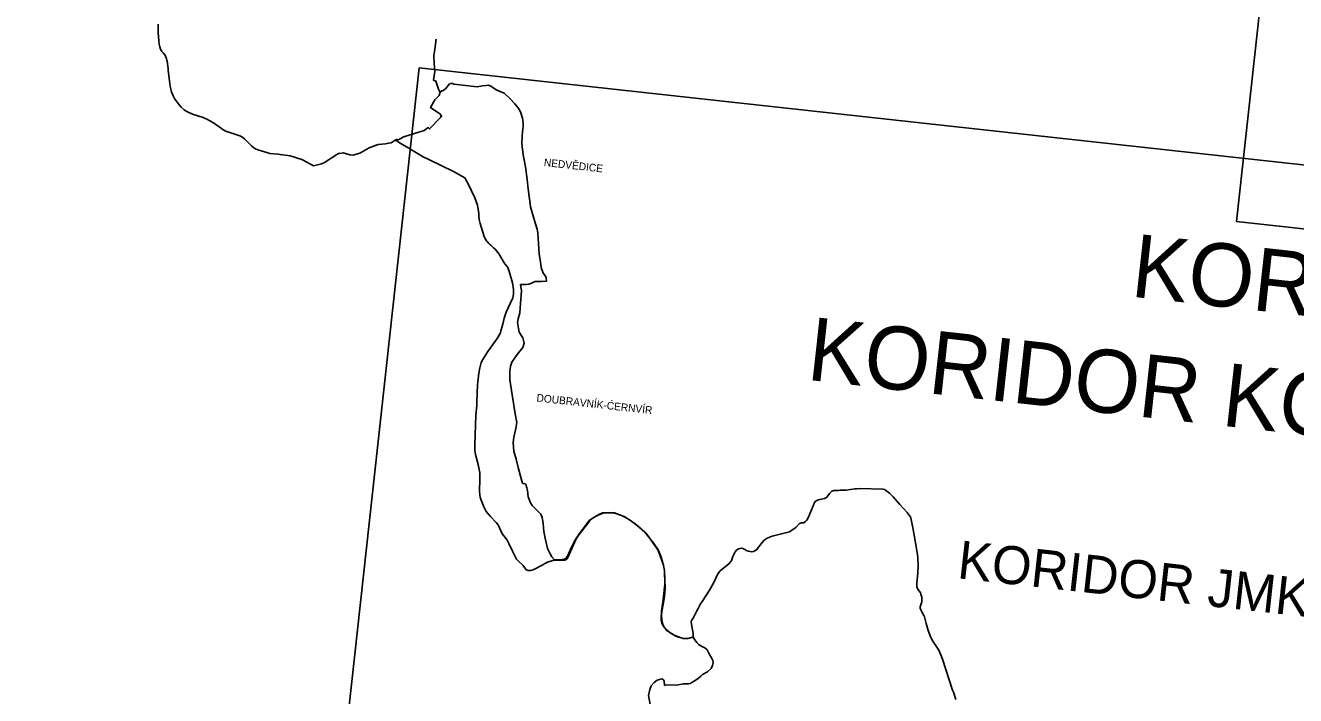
# Model space of a CAD drawing. Extents: x -678204 to -526855, y -1228851 to -1110393.
# Drawn here: x -617877 to -607858, y -1134277 to -1128993 of the extents above; entities that cross this region are included whole.
import ezdxf

# ---------------------------------------------------------------- set-up
doc = ezdxf.new("R2010")
doc.units = 0
for name, color, linetype in [('00_n_cyklo popisy', 7, 'Continuous'), ('00_n_cyklo popisy detaily', 7, 'Continuous'), ('00_n_cyklo prujezdne podminecne rekreacni hlavni', 7, 'Continuous'), ('00_n_cyklo prujezdne rekreacni hlavni', 7, 'Continuous'), ('00_n_cyklo realizace rekreacni hlavni', 7, 'Continuous'), ('00_n_cyklo studie rekreacni hlavni', 7, 'Continuous'), ('00_n_cyklo trasovani rekreacni hlavni', 7, 'Continuous'), ('00_n_legenda popisy_hlavni', 7, 'Continuous'), ('_HELP BIG', 7, 'Continuous'), ('trasy_0001', 7, 'Continuous')]:
    doc.layers.add(name, color=color, linetype=linetype)

msp = doc.modelspace()

# ---------------------------------------------------------------- linework, layer by layer
at = {"layer": '00_n_cyklo prujezdne podminecne rekreacni hlavni'}
for points in [[(-613956, -1129833), (-613951, -1129791), (-613952, -1129763), (-613955, -1129724), (-613973, -1129675), (-613990, -1129643), (-614017, -1129612), (-614054, -1129572), (-614102, -1129526), (-614163, -1129500), (-614183, -1129488), (-614205, -1129472), (-614224, -1129465), (-614242, -1129466), (-614273, -1129470), (-614314, -1129477), (-614498, -1129456), (-614507, -1129452), (-614522, -1129450), (-614532, -1129453), (-614562, -1129491), (-614582, -1129505), (-614603, -1129513)], [(-613905, -1130329), (-613906, -1130320), (-613915, -1130260), (-613920, -1130209), (-613933, -1130109), (-613940, -1130067), (-613950, -1130013), (-613960, -1129947), (-613962, -1129919), (-613959, -1129868), (-613956, -1129833)], [(-613768, -1131009), (-613770, -1130982), (-613778, -1130964), (-613794, -1130946), (-613808, -1130902), (-613815, -1130856), (-613824, -1130796), (-613834, -1130628), (-613841, -1130600), (-613857, -1130549), (-613874, -1130487), (-613892, -1130423), (-613901, -1130358), (-613905, -1130329)]]:
    msp.add_lwpolyline(points, dxfattribs=at)
at = {"layer": '00_n_cyklo prujezdne rekreacni hlavni'}
for points in [[(-614603, -1129513), (-614611, -1129511), (-614618, -1129496), (-614639, -1129432), (-614645, -1129429), (-614658, -1129425), (-614649, -1129356), (-614652, -1129291), (-614655, -1129233), (-614647, -1129181), (-614637, -1129101)], [(-614603, -1129513), (-614607, -1129527), (-614613, -1129546), (-614649, -1129580), (-614682, -1129640), (-614607, -1129690), (-614595, -1129706), (-614604, -1129720), (-614689, -1129809), (-614701, -1129799), (-614733, -1129822), (-614884, -1129868), (-614899, -1129873), (-614911, -1129881), (-614927, -1129891), (-614932, -1129893), (-614939, -1129894), (-614948, -1129892), (-614954, -1129893), (-614958, -1129897), (-614959, -1129906)], [(-613972, -1131035), (-613928, -1131036), (-613906, -1131033), (-613890, -1131029), (-613874, -1131019), (-613857, -1131012), (-613835, -1131011), (-613807, -1131012), (-613768, -1131009)], [(-610539, -1134307), (-610557, -1134251), (-610563, -1134234), (-610644, -1133990), (-610656, -1133955), (-610672, -1133919), (-610719, -1133848), (-610736, -1133820), (-610756, -1133764), (-610771, -1133709), (-610785, -1133657), (-610790, -1133645), (-610807, -1133617), (-610813, -1133601), (-610818, -1133588), (-610818, -1133577), (-610805, -1133538), (-610807, -1133502), (-610813, -1133477), (-610816, -1133467), (-610836, -1133440), (-610845, -1133422), (-610846, -1133390), (-610838, -1133308), (-610836, -1133255), (-610837, -1133191), (-610839, -1133168), (-610847, -1133117), (-610875, -1132968), (-610893, -1132876), (-610899, -1132866), (-610923, -1132834), (-610980, -1132771), (-611033, -1132711), (-611062, -1132680), (-611092, -1132656), (-611100, -1132652), (-611116, -1132649), (-611293, -1132645), (-611320, -1132646), (-611335, -1132648), (-611404, -1132657), (-611450, -1132657), (-611466, -1132660), (-611501, -1132660), (-611516, -1132666), (-611533, -1132681), (-611559, -1132715), (-611573, -1132724), (-611611, -1132731), (-611629, -1132736), (-611640, -1132741), (-611651, -1132750), (-611704, -1132876), (-611713, -1132893), (-611723, -1132904), (-611734, -1132913), (-611740, -1132916), (-611756, -1132914), (-611771, -1132920), (-611801, -1132952), (-611850, -1132985), (-611871, -1132992), (-611987, -1133020), (-612025, -1133036), (-612049, -1133052), (-612066, -1133069), (-612109, -1133129), (-612133, -1133142), (-612146, -1133143), (-612174, -1133139), (-612191, -1133132), (-612197, -1133128), (-612217, -1133117), (-612229, -1133114), (-612243, -1133117), (-612257, -1133122), (-612267, -1133131), (-612279, -1133144), (-612298, -1133180), (-612308, -1133211), (-612313, -1133220), (-612331, -1133241), (-612380, -1133280), (-612396, -1133293), (-612415, -1133317), (-612446, -1133385), (-612481, -1133445), (-612540, -1133536), (-612556, -1133562), (-612561, -1133569), (-612569, -1133585), (-612581, -1133608), (-612611, -1133666), (-612623, -1133685), (-612625, -1133699), (-612623, -1133717), (-612609, -1133788), (-612609, -1133806), (-612610, -1133812)], [(-612830, -1134196), (-612802, -1134192), (-612745, -1134195), (-612687, -1134183), (-612661, -1134183), (-612646, -1134184), (-612633, -1134181), (-612595, -1134157), (-612568, -1134139), (-612549, -1134125), (-612537, -1134112), (-612498, -1134089), (-612468, -1134064), (-612457, -1134041), (-612451, -1134016), (-612454, -1134000), (-612464, -1133978), (-612480, -1133952), (-612500, -1133916), (-612517, -1133901), (-612546, -1133888), (-612564, -1133875), (-612582, -1133859), (-612599, -1133836), (-612611, -1133812), (-612616, -1133816), (-612652, -1133827), (-612690, -1133828), (-612747, -1133808), (-612792, -1133783), (-612824, -1133756), (-612841, -1133734), (-612855, -1133697), (-612861, -1133649), (-612856, -1133613), (-612847, -1133558), (-612837, -1133493), (-612832, -1133434), (-612834, -1133359), (-612837, -1133296), (-612844, -1133248), (-612872, -1133168), (-612889, -1133127), (-612931, -1133066), (-612983, -1132994), (-613028, -1132954), (-613079, -1132916), (-613134, -1132879), (-613176, -1132856), (-613231, -1132837), (-613271, -1132833), (-613300, -1132835), (-613324, -1132837), (-613350, -1132847), (-613385, -1132868), (-613429, -1132897), (-613452, -1132925), (-613513, -1133006), (-613544, -1133055), (-613577, -1133125), (-613606, -1133189), (-613624, -1133202), (-613662, -1133206), (-613704, -1133206), (-613725, -1133184), (-613738, -1133160), (-613759, -1133116), (-613778, -1133037), (-613788, -1132983), (-613793, -1132920), (-613798, -1132886), (-613802, -1132872), (-613812, -1132847), (-613812, -1132847)]]:
    msp.add_lwpolyline(points, dxfattribs=at)
at = {"layer": '00_n_cyklo realizace rekreacni hlavni'}
msp.add_lwpolyline([(-612737, -1134640), (-612763, -1134615), (-612790, -1134591), (-612820, -1134564), (-612843, -1134539), (-612892, -1134493), (-612915, -1134461), (-612927, -1134438), (-612940, -1134395), (-612950, -1134347), (-612961, -1134275), (-612953, -1134230), (-612940, -1134199), (-612917, -1134174), (-612893, -1134155), (-612858, -1134145), (-612843, -1134153), (-612838, -1134163), (-612835, -1134197), (-612830, -1134196)], dxfattribs=at)
at = {"layer": '00_n_cyklo studie rekreacni hlavni'}
msp.add_lwpolyline([(-613812, -1132847), (-613828, -1132832), (-613864, -1132795), (-613880, -1132778), (-613892, -1132756), (-613911, -1132709), (-613918, -1132659), (-613923, -1132640), (-613931, -1132612), (-613937, -1132606), (-613950, -1132607), (-613955, -1132601), (-613965, -1132575), (-613990, -1132479), (-614007, -1132414), (-614025, -1132351), (-614031, -1132281), (-614024, -1132240), (-614008, -1132172), (-614001, -1132124), (-614014, -1132055), (-614055, -1131788), (-614057, -1131721), (-614051, -1131680), (-614041, -1131648), (-613997, -1131587), (-613954, -1131532), (-613944, -1131499), (-613954, -1131457), (-613982, -1131412), (-613989, -1131382), (-613995, -1131336), (-613990, -1131306), (-613978, -1131259), (-613973, -1131185), (-613965, -1131086), (-613972, -1131035)], dxfattribs=at)
at = {"layer": '00_n_cyklo trasovani rekreacni hlavni'}
for points in [[(-614603, -1129513), (-614611, -1129511), (-614618, -1129496), (-614639, -1129432), (-614645, -1129429), (-614658, -1129425), (-614649, -1129356), (-614652, -1129291), (-614655, -1129233), (-614647, -1129181), (-614637, -1129101)], [(-614603, -1129513), (-614607, -1129527), (-614613, -1129546), (-614649, -1129580), (-614682, -1129640), (-614607, -1129690), (-614595, -1129706), (-614604, -1129720), (-614689, -1129809), (-614701, -1129799), (-614733, -1129822), (-614884, -1129868), (-614899, -1129873), (-614911, -1129881), (-614927, -1129891), (-614932, -1129893), (-614939, -1129894), (-614948, -1129892), (-614954, -1129893), (-614958, -1129897), (-614959, -1129906)], [(-613956, -1129833), (-613951, -1129791), (-613952, -1129763), (-613955, -1129724), (-613973, -1129675), (-613990, -1129643), (-614017, -1129612), (-614054, -1129572), (-614102, -1129526), (-614163, -1129500), (-614183, -1129488), (-614205, -1129472), (-614224, -1129465), (-614242, -1129466), (-614273, -1129470), (-614314, -1129477), (-614498, -1129456), (-614507, -1129452), (-614522, -1129450), (-614532, -1129453), (-614562, -1129491), (-614582, -1129505), (-614603, -1129513)], [(-613905, -1130329), (-613906, -1130320), (-613915, -1130260), (-613920, -1130209), (-613933, -1130109), (-613940, -1130067), (-613950, -1130013), (-613960, -1129947), (-613962, -1129919), (-613959, -1129868), (-613956, -1129833)], [(-613768, -1131009), (-613770, -1130982), (-613778, -1130964), (-613794, -1130946), (-613808, -1130902), (-613815, -1130856), (-613824, -1130796), (-613834, -1130628), (-613841, -1130600), (-613857, -1130549), (-613874, -1130487), (-613892, -1130423), (-613901, -1130358), (-613905, -1130329)], [(-613972, -1131035), (-613928, -1131036), (-613906, -1131033), (-613890, -1131029), (-613874, -1131019), (-613857, -1131012), (-613835, -1131011), (-613807, -1131012), (-613768, -1131009)], [(-613812, -1132847), (-613828, -1132832), (-613864, -1132795), (-613880, -1132778), (-613892, -1132756), (-613911, -1132709), (-613918, -1132659), (-613923, -1132640), (-613931, -1132612), (-613937, -1132606), (-613950, -1132607), (-613955, -1132601), (-613965, -1132575), (-613990, -1132479), (-614007, -1132414), (-614025, -1132351), (-614031, -1132281), (-614024, -1132240), (-614008, -1132172), (-614001, -1132124), (-614014, -1132055), (-614055, -1131788), (-614057, -1131721), (-614051, -1131680), (-614041, -1131648), (-613997, -1131587), (-613954, -1131532), (-613944, -1131499), (-613954, -1131457), (-613982, -1131412), (-613989, -1131382), (-613995, -1131336), (-613990, -1131306), (-613978, -1131259), (-613973, -1131185), (-613965, -1131086), (-613972, -1131035)], [(-610539, -1134307), (-610557, -1134251), (-610563, -1134234), (-610644, -1133990), (-610656, -1133955), (-610672, -1133919), (-610719, -1133848), (-610736, -1133820), (-610756, -1133764), (-610771, -1133709), (-610785, -1133657), (-610790, -1133645), (-610807, -1133617), (-610813, -1133601), (-610818, -1133588), (-610818, -1133577), (-610805, -1133538), (-610807, -1133502), (-610813, -1133477), (-610816, -1133467), (-610836, -1133440), (-610845, -1133422), (-610846, -1133390), (-610838, -1133308), (-610836, -1133255), (-610837, -1133191), (-610839, -1133168), (-610847, -1133117), (-610875, -1132968), (-610893, -1132876), (-610899, -1132866), (-610923, -1132834), (-610980, -1132771), (-611033, -1132711), (-611062, -1132680), (-611092, -1132656), (-611100, -1132652), (-611116, -1132649), (-611293, -1132645), (-611320, -1132646), (-611335, -1132648), (-611404, -1132657), (-611450, -1132657), (-611466, -1132660), (-611501, -1132660), (-611516, -1132666), (-611533, -1132681), (-611559, -1132715), (-611573, -1132724), (-611611, -1132731), (-611629, -1132736), (-611640, -1132741), (-611651, -1132750), (-611704, -1132876), (-611713, -1132893), (-611723, -1132904), (-611734, -1132913), (-611740, -1132916), (-611756, -1132914), (-611771, -1132920), (-611801, -1132952), (-611850, -1132985), (-611871, -1132992), (-611987, -1133020), (-612025, -1133036), (-612049, -1133052), (-612066, -1133069), (-612109, -1133129), (-612133, -1133142), (-612146, -1133143), (-612174, -1133139), (-612191, -1133132), (-612197, -1133128), (-612217, -1133117), (-612229, -1133114), (-612243, -1133117), (-612257, -1133122), (-612267, -1133131), (-612279, -1133144), (-612298, -1133180), (-612308, -1133211), (-612313, -1133220), (-612331, -1133241), (-612380, -1133280), (-612396, -1133293), (-612415, -1133317), (-612446, -1133385), (-612481, -1133445), (-612540, -1133536), (-612556, -1133562), (-612561, -1133569), (-612569, -1133585), (-612581, -1133608), (-612611, -1133666), (-612623, -1133685), (-612625, -1133699), (-612623, -1133717), (-612609, -1133788), (-612609, -1133806), (-612610, -1133812)], [(-612830, -1134196), (-612802, -1134192), (-612745, -1134195), (-612687, -1134183), (-612661, -1134183), (-612646, -1134184), (-612633, -1134181), (-612595, -1134157), (-612568, -1134139), (-612549, -1134125), (-612537, -1134112), (-612498, -1134089), (-612468, -1134064), (-612457, -1134041), (-612451, -1134016), (-612454, -1134000), (-612464, -1133978), (-612480, -1133952), (-612500, -1133916), (-612517, -1133901), (-612546, -1133888), (-612564, -1133875), (-612582, -1133859), (-612599, -1133836), (-612611, -1133812), (-612616, -1133816), (-612652, -1133827), (-612690, -1133828), (-612747, -1133808), (-612792, -1133783), (-612824, -1133756), (-612841, -1133734), (-612855, -1133697), (-612861, -1133649), (-612856, -1133613), (-612847, -1133558), (-612837, -1133493), (-612832, -1133434), (-612834, -1133359), (-612837, -1133296), (-612844, -1133248), (-612872, -1133168), (-612889, -1133127), (-612931, -1133066), (-612983, -1132994), (-613028, -1132954), (-613079, -1132916), (-613134, -1132879), (-613176, -1132856), (-613231, -1132837), (-613271, -1132833), (-613300, -1132835), (-613324, -1132837), (-613350, -1132847), (-613385, -1132868), (-613429, -1132897), (-613452, -1132925), (-613513, -1133006), (-613544, -1133055), (-613577, -1133125), (-613606, -1133189), (-613624, -1133202), (-613662, -1133206), (-613704, -1133206), (-613725, -1133184), (-613738, -1133160), (-613759, -1133116), (-613778, -1133037), (-613788, -1132983), (-613793, -1132920), (-613798, -1132886), (-613802, -1132872), (-613812, -1132847), (-613812, -1132847)], [(-612737, -1134640), (-612763, -1134615), (-612790, -1134591), (-612820, -1134564), (-612843, -1134539), (-612892, -1134493), (-612915, -1134461), (-612927, -1134438), (-612940, -1134395), (-612950, -1134347), (-612961, -1134275), (-612953, -1134230), (-612940, -1134199), (-612917, -1134174), (-612893, -1134155), (-612858, -1134145), (-612843, -1134153), (-612838, -1134163), (-612835, -1134197), (-612830, -1134196)]]:
    msp.add_lwpolyline(points, dxfattribs=at)
at = {"layer": '_HELP BIG'}
for points in [[(-580037, -1133644), (-608324, -1130538), (-606112, -1110393), (-577825, -1113499)], [(-617877, -1157615), (-614771, -1129327), (-594626, -1131539), (-597732, -1159827)]]:
    msp.add_lwpolyline(points, close=True, dxfattribs=at)
at = {"layer": 'trasy_0001'}
msp.add_lwpolyline([(-610539, -1134307), (-610557, -1134251), (-610563, -1134234), (-610644, -1133990), (-610656, -1133955), (-610672, -1133919), (-610719, -1133848), (-610736, -1133820), (-610756, -1133764), (-610771, -1133709), (-610785, -1133657), (-610790, -1133645), (-610807, -1133617), (-610813, -1133601), (-610818, -1133588), (-610818, -1133577), (-610805, -1133538), (-610807, -1133502), (-610813, -1133477), (-610816, -1133467), (-610836, -1133440), (-610845, -1133422), (-610846, -1133390), (-610838, -1133308), (-610836, -1133255), (-610837, -1133191), (-610839, -1133168), (-610847, -1133117), (-610875, -1132968), (-610893, -1132876), (-610899, -1132866), (-610923, -1132834), (-610980, -1132771), (-611033, -1132711), (-611062, -1132680), (-611092, -1132656), (-611100, -1132652), (-611116, -1132649), (-611293, -1132645), (-611320, -1132646), (-611335, -1132648), (-611404, -1132657), (-611450, -1132657), (-611466, -1132660), (-611501, -1132660), (-611516, -1132666), (-611533, -1132681), (-611559, -1132715), (-611573, -1132724), (-611611, -1132731), (-611629, -1132736), (-611640, -1132741), (-611651, -1132750), (-611704, -1132876), (-611713, -1132893), (-611723, -1132904), (-611734, -1132913), (-611740, -1132916), (-611756, -1132914), (-611771, -1132920), (-611801, -1132952), (-611850, -1132985), (-611871, -1132992), (-611987, -1133020), (-612025, -1133036), (-612049, -1133052), (-612066, -1133069), (-612109, -1133129), (-612133, -1133142), (-612146, -1133143), (-612174, -1133139), (-612191, -1133132), (-612197, -1133128), (-612217, -1133117), (-612229, -1133114), (-612243, -1133117), (-612257, -1133122), (-612267, -1133131), (-612279, -1133144), (-612298, -1133180), (-612308, -1133211), (-612313, -1133220), (-612331, -1133241), (-612380, -1133280), (-612396, -1133293), (-612415, -1133317), (-612446, -1133385), (-612481, -1133445), (-612540, -1133536), (-612556, -1133562), (-612561, -1133569), (-612569, -1133585), (-612581, -1133608), (-612611, -1133666), (-612623, -1133685), (-612625, -1133699), (-612623, -1133717), (-612609, -1133788), (-612609, -1133806), (-612611, -1133814), (-612615, -1133818), (-612653, -1133827), (-612659, -1133827), (-612681, -1133827), (-612704, -1133822), (-612760, -1133800), (-612809, -1133769), (-612819, -1133760), (-612844, -1133730), (-612857, -1133705), (-612863, -1133681), (-612863, -1133663), (-612860, -1133612), (-612846, -1133520), (-612833, -1133399), (-612837, -1133291), (-612840, -1133264), (-612853, -1133221), (-612864, -1133178), (-612886, -1133128), (-612920, -1133078), (-612990, -1132989), (-613051, -1132935), (-613103, -1132897), (-613155, -1132865), (-613221, -1132842), (-613247, -1132837), (-613279, -1132835), (-613307, -1132837), (-613327, -1132842), (-613360, -1132854), (-613399, -1132875), (-613428, -1132901), (-613436, -1132911), (-613511, -1133010), (-613522, -1133025), (-613536, -1133047), (-613598, -1133187), (-613605, -1133200), (-613611, -1133205), (-613623, -1133208), (-613655, -1133209), (-613693, -1133209), (-613710, -1133209), (-613717, -1133211), (-613740, -1133219), (-613753, -1133223), (-613780, -1133235), (-613796, -1133246), (-613866, -1133284), (-613879, -1133289), (-613892, -1133292), (-613912, -1133290), (-613926, -1133285), (-613952, -1133252), (-613989, -1133217), (-614003, -1133202), (-614038, -1133132), (-614063, -1133078), (-614077, -1133051), (-614102, -1133021), (-614116, -1133001), (-614148, -1132931), (-614164, -1132912), (-614209, -1132864), (-614243, -1132825), (-614264, -1132783), (-614275, -1132755), (-614283, -1132736), (-614290, -1132712), (-614293, -1132696), (-614296, -1132666), (-614293, -1132571), (-614293, -1132519), (-614297, -1132495), (-614306, -1132455), (-614328, -1132375), (-614332, -1132344), (-614333, -1132299), (-614323, -1132068), (-614317, -1131986), (-614316, -1131961), (-614310, -1131826), (-614301, -1131736), (-614293, -1131693), (-614281, -1131650), (-614270, -1131627), (-614229, -1131563), (-614208, -1131534), (-614204, -1131528), (-614156, -1131462), (-614131, -1131418), (-614126, -1131400), (-614111, -1131348), (-614101, -1131300), (-614086, -1131253), (-614033, -1131140), (-614031, -1131130), (-614026, -1131103), (-614026, -1131074), (-614034, -1131022), (-614059, -1130942), (-614072, -1130902), (-614079, -1130890), (-614093, -1130875), (-614102, -1130865), (-614135, -1130807), (-614141, -1130796), (-614172, -1130757), (-614184, -1130747), (-614206, -1130726), (-614210, -1130722), (-614222, -1130712), (-614235, -1130697), (-614240, -1130691), (-614255, -1130664), (-614271, -1130614), (-614290, -1130554), (-614298, -1130523), (-614300, -1130494), (-614301, -1130475), (-614312, -1130409), (-614333, -1130352), (-614385, -1130242), (-614412, -1130194), (-614501, -1130146), (-614689, -1130053), (-614741, -1130028), (-614833, -1129974), (-614867, -1129954), (-614926, -1129919), (-614938, -1129911), (-614958, -1129896), (-614969, -1129903), (-614993, -1129919), (-615014, -1129921), (-615037, -1129926), (-615094, -1129933), (-615102, -1129934), (-615165, -1129959), (-615239, -1130000), (-615276, -1130012), (-615293, -1130015), (-615319, -1130014), (-615371, -1129998), (-615399, -1130002), (-615408, -1130004), (-615422, -1130010), (-615519, -1130075), (-615541, -1130084), (-615606, -1130099), (-615651, -1130075), (-615696, -1130050), (-615789, -1130022), (-615885, -1130007), (-615948, -1130002), (-615965, -1129998), (-616043, -1129974), (-616056, -1129969), (-616073, -1129960), (-616094, -1129943), (-616149, -1129887), (-616169, -1129871), (-616186, -1129863), (-616281, -1129833), (-616286, -1129831), (-616311, -1129818), (-616394, -1129762), (-616422, -1129746), (-616440, -1129736), (-616476, -1129719), (-616559, -1129693), (-616599, -1129675), (-616614, -1129667), (-616625, -1129659), (-616649, -1129637), (-616676, -1129605), (-616677, -1129602), (-616698, -1129574), (-616713, -1129548), (-616726, -1129516), (-616733, -1129484), (-616739, -1129454), (-616750, -1129347), (-616751, -1129333), (-616759, -1129276), (-616761, -1129267), (-616764, -1129256), (-616776, -1129227), (-616791, -1129209), (-616800, -1129198), (-616811, -1129180), (-616818, -1129162), (-616823, -1129141), (-616824, -1129115), (-616830, -1129050), (-616830, -1128982)], dxfattribs=at)

# ---------------------------------------------------------------- texts
at = {"layer": '00_n_cyklo popisy'}
msp.add_text('KORIDOR JMK KCT 1', height=300, rotation=353.6836, dxfattribs=at).set_placement((-610533, -1133351))
at = {"layer": '00_n_cyklo popisy detaily'}
for s, p in [('NEDVĚDICE', (-613790, -1130101)), ('DOUBRAVNÍK-ĆERNVÍR', (-613848, -1131957))]:
    msp.add_text(s, height=60, rotation=353.6836, dxfattribs=at).set_placement(p)
at = {"layer": '00_n_legenda popisy_hlavni'}
for s, p in [('KORIDOR EV4 BRNO-KUŘIM-TIŠNOV', (-609167, -1131130)), ('KORIDOR KČT 1 BRNO-V.BÍTÝŠKA-TIŠNOV', (-611722, -1131786))]:
    msp.add_text(s, height=497.66, rotation=353.6836, dxfattribs=at).set_placement(p)

doc.saveas('drawing.dxf')
